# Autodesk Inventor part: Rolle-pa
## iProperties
Created: 2012-11
Part Number: Rolle-pa
Document SubType Name: Modeling
Designer: Palme
Density: 1 g/cm^3
Author: Palme
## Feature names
1. Umdrehung1 [Revolution]
